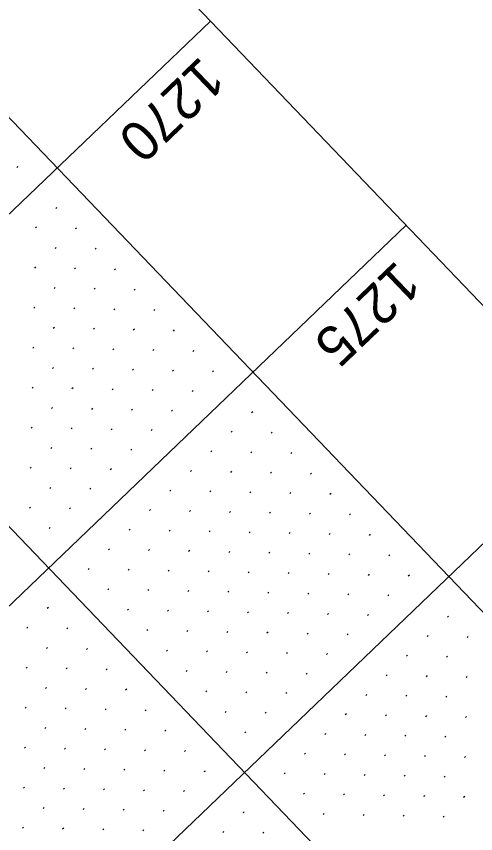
# Model space of a CAD drawing. Extents: x 2148987 to 2151117, y 142806 to 144993.
# Drawn here: x 2150262.3 to 2150343.4, y 144504.6 to 144649 of the extents above; entities that cross this region are included whole.
import ezdxf

# ---------------------------------------------------------------- set-up
doc = ezdxf.new("R2010")
doc.units = 0
for name, color, linetype in [('PR_PIER_PH3', 7, 'Continuous'), ('PR_Road_Concrete', 7, 'Continuous'), ('SHT_Profile_Grid_Minor', 7, 'Continuous'), ('Wall D Bore', 7, 'Continuous')]:
    doc.layers.add(name, color=color, linetype=linetype)

msp = doc.modelspace()

# ---------------------------------------------------------------- linework, layer by layer
at = {"layer": 'PR_PIER_PH3'}
for p, q in [((2150164.2, 144659.82), (2150510.15, 144298.83)), ((2150296.56, 144648.16), (2149159.43, 143558.42)), ((2150331.16, 144612.07), (2149194.02, 143522.32)), ((2150365.75, 144575.97), (2149228.62, 143486.22))]:
    msp.add_line(p, q, dxfattribs=at)
at = {"layer": 'PR_Road_Concrete'}
msp.add_line((2150200.3, 144694.42), (2150546.25, 144333.42), dxfattribs=at)
msp.add_lwpolyline([(2150941.76, 143974.91), (2149804.63, 142885.16), (2149078.13, 143643.25), (2150215.26, 144733)], close=True, dxfattribs=at)
at = {"layer": 'SHT_Profile_Grid_Minor'}
for p, q in [((2150262.51, 144622.46), (2150262.33, 144622.28)), ((2150269.43, 144615.24), (2150269.25, 144615.06)), ((2150265.82, 144611.78), (2150265.64, 144611.6)), ((2150272.89, 144611.63), (2150272.71, 144611.45)), ((2150269.28, 144608.17), (2150269.1, 144607.99)), ((2150276.35, 144608.02), (2150276.17, 144607.84)), ((2150265.67, 144604.71), (2150265.49, 144604.53)), ((2150272.74, 144604.56), (2150272.56, 144604.38)), ((2150279.81, 144604.41), (2150279.63, 144604.23)), ((2150269.13, 144601.1), (2150268.95, 144600.92)), ((2150276.2, 144600.95), (2150276.02, 144600.77)), ((2150283.27, 144600.8), (2150283.08, 144600.62)), ((2150265.52, 144597.64), (2150265.34, 144597.46)), ((2150272.59, 144597.49), (2150272.41, 144597.31)), ((2150279.66, 144597.34), (2150279.48, 144597.16)), ((2150286.72, 144597.19), (2150286.54, 144597.01)), ((2150268.98, 144594.03), (2150268.8, 144593.85)), ((2150276.05, 144593.88), (2150275.87, 144593.7)), ((2150283.12, 144593.73), (2150282.93, 144593.55)), ((2150290.18, 144593.58), (2150290, 144593.4)), ((2150265.37, 144590.57), (2150265.19, 144590.39)), ((2150272.44, 144590.42), (2150272.26, 144590.24)), ((2150279.51, 144590.27), (2150279.32, 144590.09)), ((2150286.57, 144590.12), (2150286.39, 144589.94)), ((2150293.64, 144589.97), (2150293.46, 144589.79)), ((2150268.83, 144586.96), (2150268.65, 144586.78)), ((2150275.9, 144586.81), (2150275.71, 144586.63)), ((2150282.96, 144586.66), (2150282.78, 144586.48)), ((2150290.03, 144586.51), (2150289.85, 144586.33)), ((2150297.1, 144586.36), (2150296.92, 144586.18)), ((2150265.22, 144583.5), (2150265.04, 144583.32)), ((2150272.29, 144583.35), (2150272.1, 144583.17)), ((2150279.35, 144583.2), (2150279.17, 144583.02)), ((2150286.42, 144583.05), (2150286.24, 144582.87)), ((2150293.49, 144582.9), (2150293.31, 144582.72)), ((2150268.68, 144579.89), (2150268.49, 144579.72)), ((2150275.74, 144579.74), (2150275.56, 144579.56)), ((2150282.81, 144579.59), (2150282.63, 144579.41)), ((2150289.88, 144579.44), (2150289.7, 144579.26)), ((2150304.02, 144579.14), (2150303.84, 144578.96)), ((2150265.07, 144576.43), (2150264.88, 144576.26)), ((2150272.13, 144576.28), (2150271.95, 144576.11)), ((2150279.2, 144576.13), (2150279.02, 144575.95)), ((2150286.27, 144575.98), (2150286.09, 144575.8)), ((2150300.41, 144575.68), (2150300.23, 144575.5)), ((2150307.48, 144575.53), (2150307.3, 144575.35)), ((2150268.52, 144572.82), (2150268.34, 144572.65)), ((2150275.59, 144572.67), (2150275.41, 144572.5)), ((2150282.66, 144572.52), (2150282.48, 144572.34)), ((2150296.8, 144572.22), (2150296.62, 144572.04)), ((2150303.87, 144572.07), (2150303.69, 144571.89)), ((2150310.94, 144571.92), (2150310.76, 144571.74)), ((2150264.91, 144569.36), (2150264.73, 144569.19)), ((2150271.98, 144569.21), (2150271.8, 144569.04)), ((2150279.05, 144569.06), (2150278.87, 144568.89)), ((2150293.19, 144568.76), (2150293.01, 144568.58)), ((2150300.26, 144568.61), (2150300.08, 144568.43)), ((2150307.33, 144568.46), (2150307.15, 144568.28)), ((2150314.4, 144568.31), (2150314.22, 144568.13)), ((2150268.37, 144565.75), (2150268.19, 144565.58)), ((2150275.44, 144565.6), (2150275.26, 144565.43)), ((2150289.58, 144565.3), (2150289.4, 144565.12)), ((2150296.65, 144565.15), (2150296.47, 144564.97)), ((2150303.72, 144565), (2150303.54, 144564.82)), ((2150310.79, 144564.85), (2150310.61, 144564.67)), ((2150317.86, 144564.7), (2150317.68, 144564.52)), ((2150264.76, 144562.29), (2150264.58, 144562.12)), ((2150271.83, 144562.14), (2150271.65, 144561.97)), ((2150285.97, 144561.84), (2150285.79, 144561.67)), ((2150293.04, 144561.69), (2150292.86, 144561.51)), ((2150300.11, 144561.54), (2150299.93, 144561.36)), ((2150307.18, 144561.39), (2150307, 144561.21)), ((2150314.25, 144561.24), (2150314.07, 144561.06)), ((2150321.32, 144561.09), (2150321.14, 144560.91)), ((2150268.22, 144558.68), (2150268.04, 144558.51)), ((2150282.36, 144558.38), (2150282.18, 144558.21)), ((2150289.43, 144558.23), (2150289.25, 144558.06)), ((2150296.5, 144558.08), (2150296.32, 144557.9)), ((2150303.57, 144557.93), (2150303.39, 144557.75)), ((2150310.64, 144557.78), (2150310.46, 144557.6)), ((2150317.71, 144557.63), (2150317.53, 144557.45)), ((2150324.78, 144557.48), (2150324.6, 144557.3)), ((2150278.75, 144554.92), (2150278.57, 144554.75)), ((2150285.82, 144554.77), (2150285.64, 144554.6)), ((2150292.89, 144554.62), (2150292.71, 144554.45)), ((2150299.96, 144554.47), (2150299.78, 144554.29)), ((2150307.03, 144554.32), (2150306.85, 144554.14)), ((2150314.1, 144554.17), (2150313.92, 144553.99)), ((2150321.17, 144554.02), (2150320.99, 144553.84)), ((2150328.24, 144553.87), (2150328.06, 144553.69)), ((2150275.14, 144551.46), (2150274.96, 144551.29)), ((2150282.21, 144551.31), (2150282.03, 144551.14)), ((2150289.28, 144551.16), (2150289.1, 144550.99)), ((2150296.35, 144551.01), (2150296.17, 144550.84)), ((2150303.42, 144550.86), (2150303.24, 144550.68)), ((2150310.49, 144550.71), (2150310.31, 144550.53)), ((2150317.56, 144550.56), (2150317.38, 144550.38)), ((2150324.63, 144550.41), (2150324.45, 144550.23)), ((2150331.7, 144550.26), (2150331.52, 144550.08)), ((2150278.6, 144547.85), (2150278.42, 144547.68)), ((2150285.67, 144547.7), (2150285.49, 144547.53)), ((2150292.74, 144547.55), (2150292.56, 144547.38)), ((2150299.81, 144547.4), (2150299.63, 144547.23)), ((2150306.88, 144547.25), (2150306.7, 144547.08)), ((2150313.95, 144547.1), (2150313.77, 144546.92)), ((2150321.02, 144546.95), (2150320.84, 144546.77)), ((2150328.09, 144546.8), (2150327.91, 144546.62)), ((2150267.92, 144544.54), (2150267.74, 144544.37)), ((2150282.06, 144544.24), (2150281.88, 144544.07)), ((2150289.13, 144544.09), (2150288.95, 144543.92)), ((2150296.2, 144543.94), (2150296.02, 144543.77)), ((2150303.27, 144543.79), (2150303.09, 144543.62)), ((2150310.34, 144543.64), (2150310.16, 144543.47)), ((2150317.41, 144543.49), (2150317.23, 144543.31)), ((2150324.48, 144543.34), (2150324.3, 144543.16)), ((2150338.62, 144543.04), (2150338.44, 144542.86)), ((2150264.31, 144541.08), (2150264.13, 144540.91)), ((2150271.38, 144540.93), (2150271.2, 144540.76)), ((2150285.52, 144540.63), (2150285.34, 144540.46)), ((2150292.59, 144540.48), (2150292.41, 144540.31)), ((2150299.66, 144540.33), (2150299.48, 144540.16)), ((2150306.73, 144540.18), (2150306.55, 144540.01)), ((2150313.8, 144540.03), (2150313.62, 144539.86)), ((2150320.87, 144539.88), (2150320.69, 144539.7)), ((2150335.01, 144539.58), (2150334.83, 144539.4)), ((2150342.08, 144539.43), (2150341.9, 144539.25)), ((2150267.77, 144537.47), (2150267.59, 144537.3)), ((2150274.84, 144537.32), (2150274.66, 144537.15)), ((2150288.98, 144537.02), (2150288.8, 144536.85)), ((2150296.05, 144536.87), (2150295.87, 144536.7)), ((2150303.12, 144536.72), (2150302.94, 144536.55)), ((2150310.19, 144536.57), (2150310.01, 144536.4)), ((2150317.26, 144536.42), (2150317.08, 144536.25)), ((2150331.4, 144536.12), (2150331.22, 144535.94)), ((2150338.47, 144535.97), (2150338.29, 144535.79)), ((2150264.16, 144534.01), (2150263.98, 144533.84)), ((2150271.23, 144533.86), (2150271.05, 144533.69)), ((2150278.3, 144533.71), (2150278.12, 144533.54)), ((2150292.44, 144533.41), (2150292.26, 144533.24)), ((2150299.51, 144533.26), (2150299.33, 144533.09)), ((2150306.58, 144533.11), (2150306.4, 144532.94)), ((2150313.65, 144532.96), (2150313.47, 144532.79)), ((2150327.79, 144532.66), (2150327.61, 144532.48)), ((2150334.86, 144532.51), (2150334.68, 144532.33)), ((2150341.93, 144532.36), (2150341.75, 144532.18)), ((2150267.62, 144530.4), (2150267.44, 144530.23)), ((2150274.69, 144530.25), (2150274.51, 144530.08)), ((2150281.76, 144530.1), (2150281.58, 144529.93)), ((2150295.9, 144529.8), (2150295.72, 144529.63)), ((2150302.97, 144529.65), (2150302.79, 144529.48)), ((2150310.04, 144529.5), (2150309.86, 144529.33)), ((2150324.18, 144529.2), (2150324, 144529.03)), ((2150331.25, 144529.05), (2150331.07, 144528.87)), ((2150338.32, 144528.9), (2150338.14, 144528.72)), ((2150264.01, 144526.94), (2150263.83, 144526.77)), ((2150271.08, 144526.79), (2150270.9, 144526.62)), ((2150278.15, 144526.64), (2150277.97, 144526.47)), ((2150285.22, 144526.49), (2150285.04, 144526.32)), ((2150299.36, 144526.19), (2150299.18, 144526.02)), ((2150306.43, 144526.04), (2150306.25, 144525.87)), ((2150320.57, 144525.74), (2150320.39, 144525.57)), ((2150327.64, 144525.59), (2150327.46, 144525.42)), ((2150334.71, 144525.44), (2150334.53, 144525.26)), ((2150341.78, 144525.29), (2150341.6, 144525.11)), ((2150267.47, 144523.33), (2150267.29, 144523.16)), ((2150274.54, 144523.18), (2150274.36, 144523.01)), ((2150281.61, 144523.03), (2150281.43, 144522.86)), ((2150288.68, 144522.88), (2150288.5, 144522.71)), ((2150302.82, 144522.58), (2150302.64, 144522.41)), ((2150316.96, 144522.28), (2150316.78, 144522.11)), ((2150324.03, 144522.13), (2150323.85, 144521.96)), ((2150331.1, 144521.98), (2150330.92, 144521.81)), ((2150338.17, 144521.83), (2150337.99, 144521.65)), ((2150263.86, 144519.87), (2150263.68, 144519.7)), ((2150270.93, 144519.72), (2150270.75, 144519.55)), ((2150278, 144519.57), (2150277.82, 144519.4)), ((2150285.07, 144519.42), (2150284.89, 144519.25)), ((2150292.14, 144519.27), (2150291.96, 144519.1)), ((2150313.35, 144518.82), (2150313.17, 144518.65)), ((2150320.42, 144518.67), (2150320.24, 144518.5)), ((2150327.49, 144518.52), (2150327.31, 144518.35)), ((2150334.56, 144518.37), (2150334.38, 144518.2)), ((2150341.63, 144518.22), (2150341.45, 144518.04)), ((2150267.32, 144516.26), (2150267.14, 144516.09)), ((2150274.39, 144516.11), (2150274.21, 144515.94)), ((2150281.46, 144515.96), (2150281.28, 144515.79)), ((2150288.53, 144515.81), (2150288.35, 144515.64)), ((2150295.6, 144515.66), (2150295.42, 144515.49)), ((2150309.74, 144515.36), (2150309.56, 144515.19)), ((2150316.81, 144515.21), (2150316.63, 144515.04)), ((2150323.88, 144515.06), (2150323.7, 144514.89)), ((2150330.95, 144514.91), (2150330.77, 144514.74)), ((2150338.02, 144514.76), (2150337.84, 144514.59)), ((2150263.71, 144512.8), (2150263.53, 144512.63)), ((2150270.78, 144512.65), (2150270.6, 144512.48)), ((2150277.85, 144512.5), (2150277.67, 144512.33)), ((2150284.92, 144512.35), (2150284.74, 144512.18)), ((2150291.99, 144512.2), (2150291.81, 144512.03)), ((2150313.2, 144511.75), (2150313.02, 144511.58)), ((2150320.27, 144511.6), (2150320.09, 144511.43)), ((2150327.34, 144511.45), (2150327.16, 144511.28)), ((2150334.41, 144511.3), (2150334.23, 144511.13)), ((2150341.48, 144511.15), (2150341.29, 144510.98)), ((2150267.17, 144509.19), (2150266.99, 144509.02)), ((2150274.24, 144509.04), (2150274.06, 144508.87)), ((2150281.31, 144508.89), (2150281.13, 144508.72)), ((2150288.38, 144508.74), (2150288.2, 144508.57)), ((2150302.52, 144508.44), (2150302.34, 144508.27)), ((2150316.66, 144508.14), (2150316.48, 144507.97)), ((2150323.73, 144507.99), (2150323.55, 144507.82)), ((2150330.8, 144507.84), (2150330.62, 144507.67)), ((2150337.87, 144507.69), (2150337.69, 144507.52)), ((2150263.56, 144505.73), (2150263.38, 144505.56)), ((2150270.63, 144505.58), (2150270.45, 144505.41)), ((2150277.7, 144505.43), (2150277.52, 144505.26)), ((2150284.77, 144505.28), (2150284.59, 144505.11)), ((2150298.91, 144504.98), (2150298.73, 144504.81)), ((2150305.98, 144504.83), (2150305.8, 144504.66))]:
    msp.add_line(p, q, dxfattribs=at)

# ---------------------------------------------------------------- texts
at = {"layer": 'Wall D Bore'}
for s, p in [('1270', (2150294.85, 144642.15)), ('1275', (2150329.45, 144606.05))]:
    msp.add_text(s, height=7, rotation=223.7809, dxfattribs=at).set_placement(p)

doc.saveas('drawing.dxf')
